Omron CX-Programmer project NuevoProyecto (CX-Programmer 9.50)

# PLC NewPLC1: CP1L-E EM

## Program P1_1 (cyclic task 0)
Local symbols
B 100.00 BOOL
Etapa_0 10.00 BOOL
Etapa_1 10.01 BOOL
Etapa_2 10.02 BOOL
Etapa_3 10.03 BOOL
p 0.00 BOOL

### Section Sección1_Programa_principal
; Programa principal (Etapas 0 ... 3)

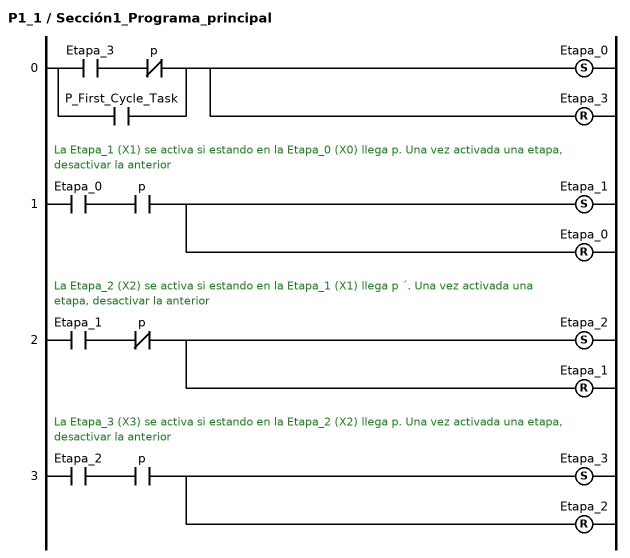
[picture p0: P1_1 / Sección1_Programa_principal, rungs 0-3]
; rung 0
LD Etapa_3
ANDNOT p
OR P_First_Cycle_Task
SET Etapa_0  // La Etapa_0 (X0) se activa si estando en la Etapa_3 (X3) llega p´ o bien con la Inicializacion del GRAFCET (P_First_Cycle)
RSET Etapa_3  // Una vez activada una etapa, desactivar la anterior
; rung 1: La Etapa_1 (X1) se activa si estando en la Etapa_0 (X0) llega p. Una vez activada una etapa, desactivar la anterior
LD Etapa_0
AND p
SET Etapa_1
RSET Etapa_0
; rung 2: La Etapa_2 (X2) se activa si estando en la Etapa_1 (X1) llega p ´. Una vez activada una etapa, desactivar la anterior
LD Etapa_1
ANDNOT p
SET Etapa_2
RSET Etapa_1
; rung 3: La Etapa_3 (X3) se activa si estando en la Etapa_2 (X2) llega p. Una vez activada una etapa, desactivar la anterior
LD Etapa_2
AND p
SET Etapa_3
RSET Etapa_2

### Section Sección2_Salida

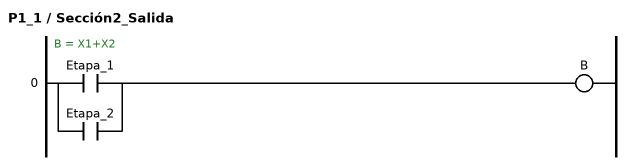
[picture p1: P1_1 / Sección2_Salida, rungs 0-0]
; rung 0: B = X1+X2
LD Etapa_1
OR Etapa_2
OUT B

### Section Sección3_END
; rung 0: Fin de programa
END(001)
